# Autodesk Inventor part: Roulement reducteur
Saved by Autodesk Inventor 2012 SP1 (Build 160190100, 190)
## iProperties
Created: 2014-12
Part Number: Roulement reducteur
Material: Default
Document SubType Name: Modeling
Designer: Bruno
Density: 1 g/cm^3
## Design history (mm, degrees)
node "Roulement reducteur1"
node "Roulement reducteur"
node "Base1"
